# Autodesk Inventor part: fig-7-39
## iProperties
Shininess: 77.0
Length Units: 11269
Angle Units: 11279
Time Units: 11290
Mass Units: 11283
Length Display Precision: 3
Angle Display Precision: 2
Created: 2002-01
Part Number: fig-7-39
Document SubType Name: Modeling
Designer: ***
Density: 0.0
Volumn: 0.0
Area: 0.0
PropertySet Name: Model Information
Control State: 0
Master: False
Checked Out: False
Author: ***
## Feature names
1. Extrusion1
2. Fillet1
3. Extrusion2
4. Extrusion3
5. Chamfer1
